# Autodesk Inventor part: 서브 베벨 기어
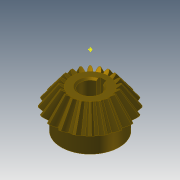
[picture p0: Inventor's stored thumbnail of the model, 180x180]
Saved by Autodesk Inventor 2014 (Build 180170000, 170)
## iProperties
Created: 2014-10
Part Number: 서브 베벨 기어
Material: Steel, Mild
Document SubType Name: Modeling
Designer: KYOUNG IL JANG
Categories: <?xml version="1.0" encoding="UTF-16"?> <MemberInstance><Categories><FamilyTemplate><FamilyTemplateParameter ValueType="xs:double" Id="1" ObjectReferenceKey="da
Mass: 134.866 g
Surface Area: 63.6518 cm^2
Volume: 17.1585 cm^3
Density: 7.86 g/cm^3
Appearance: Brindle
CustomPartVersion: 1
Company: 한국ATC센터
Author: KYOUNG IL JANG
Revision Number: 1
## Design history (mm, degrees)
node "맨 위 점"
node "메쉬 평면2"
sketch "톱니 본체 스케치"
  geometry: L1 (0, 0)-(18.003, -31.331); L2 (18.003, -31.331)-(21.664, -28.891); L3 (21.664, -28.891)-(0, 0); L4 (20, -30)-(0, 0); L5 (10.813, -18.818)-(13.012, -17.352); L6 (18.003, -31.331)-(10.813, -18.818); L7 (21.664, -28.891)-(13.012, -17.352); L8 (0, -39.387)-(0, 6.564) reference; L9 (0, -30)-(21.664, -30)
  constraints: 16 end point, 4 point on line, 3 perpendicular, 2 collinear, 1 horizontal alignment, 1 vertical alignment
  dimensions: "d0" = 40 diameter of L4.start L8 (= da_de); "d1" = 36.00616 diameter of L1.end L8 (= da_dfe); "d2" = 43.3282 diameter of L2.end L8 (= da_dae); "d3" = 14.4 distance between parallel lines of L2 L5 (= da_b); "d4" = 28.8906 vertical distance of L2.end L1.start (= da_ve)
revolve "톱니 본체" sketch "톱니 본체 스케치" stored, may be unused: angle "d5" = 90 deg
node "시작점"
node "톱니 평면"
sketch "시작 스케치"
  geometry: L1 (0, -23.505)-(0, 10.645) reference; L2 (-0.834, -2.928)-(0.834, -2.928); A1 r 8.898 centre (-9.698, -3.713) between (-0.834, -2.928) and (-3.903, 3.04); A2 r 8.898 centre (9.698, -3.713) between (3.903, 3.04) and (0.834, -2.928); A3 r 27.357 centre (0, -24.037) between (3.903, 3.04) and (-3.903, 3.04); 1 further point
  constraints: 6 point on circle, 3 centre point, 3 symmetric about line, 2 end point, 1 coincident, 1 perpendicular, 1 other
  dimensions: "d7" = 8.89846 radius of A1 (= fd_rr); "d8" = 9.69794 horizontal distance of point (0, -24.037) A1.centre (= fd_x); "d9" = 20.32439 vertical distance of point (0, -24.037) A1.centre (= fd_y); "d57" = 27.35701 radius of A3 (= 0.5 x fd_dva + 0.3 x da_he); "d58" = 21.10901 distance from line of A3.centre L2 (= 0.5 x fd_dva - 1.12 x da_he)
node "끝점"
  node "끝 평면"
sketch "3D 스케치 오른쪽"
  node "Helical Curve Right" dims "d65" = 229.90621 (computed from da_dm, da_delta, da_beta), "d66" = 31.5, "d67" = 40 (= da_de), "d68" = -5.88003 (= -da_delta), "d69" = 12.16458 (computed from fd_loft, da_delta)
node "끝 평면 오른쪽"
sketch "끝 스케치 오른쪽"
  geometry: L1 (0, -22.649)-(0, 12.15) reference; L2 (-0.497, -1.72)-(0.497, -1.72); A1 r 5.299 centre (-5.775, -2.187) between (-0.497, -1.72) and (-2.324, 1.834); A2 r 5.299 centre (5.775, -2.187) between (2.324, 1.834) and (0.497, -1.72); A3 r 16.291 centre (0, -14.29) between (2.324, 1.834) and (-2.324, 1.834); 1 further point
  constraints: 6 point on circle, 3 centre point, 3 symmetric about line, 2 end point, 1 coincident, 1 perpendicular, 1 other
  dimensions: "d70" = 5.77526 horizontal distance of A3.centre A1.centre (computed from fd_x, fd_ratio); "d71" = 12.10346 vertical distance of point (0, -14.29) A1.centre (computed from fd_y, fd_ratio); "d72" = 5.29916 radius of A1 (computed from fd_rr, fd_ratio); "d73" = 12.57071 distance from line of point (0, -14.29) L2 (computed from d58, fd_ratio); "d74" = 16.29149 radius of A3 (computed from d57, fd_ratio)
feature "로프트 오른쪽" sketch "끝 스케치 오른쪽" dims "d75" = 0, "d77" = 0, "d79" = 0, "d80" = 90 deg, "d85" = 20, "d92" = 90 deg, "d93" = 90 deg, "da_teethtype" = 0 [user parameter]
sketch "3D 스케치 왼쪽"
  node "Helical Curve Left" dims "d26" = 229.90621 (computed from da_dm, da_delta, da_beta), "d27" = 12.16458 (computed from fd_loft, da_delta), "d28" = 40 (= da_de), "d29" = -5.88003 (= -da_delta)
node "끝 평면 왼쪽"
sketch "끝 스케치 왼쪽" dims "d56" = 10.82768 (derived)
  geometry: L1 (0, -35.087)-(0, 18.089) reference; L2 (-0.497, -1.716)-(0.497, -1.716); A1 r 5.299 centre (-5.775, -2.183) between (-0.497, -1.716) and (-2.324, 1.838); A2 r 5.299 centre (5.775, -2.183) between (2.324, 1.838) and (0.497, -1.716); A3 r 16.291 centre (0, -14.287) between (2.324, 1.838) and (-2.324, 1.838); 2 further points; 1 other entity
  constraints: 6 point on circle, 3 centre point, 3 symmetric about line, 2 end point, 1 coincident, 2 other
  dimensions: "d30" = 5.29916 radius of A1 (computed from fd_rr, fd_ratio); "d31" = 5.77526 horizontal distance of point (0, -14.287) A1.centre (computed from fd_x, fd_ratio); "d32" = 12.10346 vertical distance of A1.centre point (0, -14.287) (computed from fd_y, fd_ratio); "d61" = 16.29149 radius of A3 (computed from d57, fd_ratio); "d62" = 12.57071 distance from line of point (0, -14.287) L2 (computed from d58, fd_ratio)
feature "로프트 왼쪽" sketch "끝 스케치 왼쪽" dims "d35" = 0, "d37" = 0, "d39" = 0, "d40" = 90 deg, "d84" = 10, "d90" = 90 deg, "d91" = 90 deg, "da_teethtype" = 0 [user parameter]
sketch "본체 스케치"
  geometry: L1 (0, -35.038)-(0, -19.531) reference; L2 (18.003, -31.331)-(10.813, -18.818) reference; L3 (10.813, -18.818)-(0, -18.818); L4 (18.003, -31.331)-(0, -31.331)
  constraints: 4 end point, 2 perpendicular, 2 point on line
revolve "본체 고정" sketch "본체 스케치" stored, may be unused: angle "d46" = 90 deg
sketch "Sketch6"
  geometry: L1 (20, -30)-(0, 0) reference; L2 (0, -37.8)-(0, 6.3) reference
feature "피치 지름" sketch "Sketch6" dims angle "d47" = 90 deg
sketch "스케치8"
  geometry: C1 r 17 at (0, 0); 1 further point
  constraints: 1 centre point, 1 coincident
  dimensions: "d94" = 34 diameter of C1
extrude "돌출1" join sketch "스케치8" distance "d95" = 10; taper "d96" = 0 deg
sketch "스케치9"
  geometry: 1 further point
hole "구멍1" sketch "스케치9" diameter "d97" = 12; stored, may be unused: countersink angle "d101" = 90 deg, drill point angle "d103" = 118 deg; dims "d98" = 6, "d99" = 4, "d100" = 2, "d102" = 8
sketch "스케치12"
  geometry: L1 (-2, 5.657)-(-2, 7.8); L2 (-2, 7.8)-(2, 7.8); L3 (2, 7.8)-(2, 5.657); A1 r 6 centre (0, 0) between (-2, 5.657) and (2, 5.657) reference; 1 further point
  constraints: 6 end point, 2 parallel, 2 point on circle, 1 perpendicular, 1 vertical
  dimensions: "d104" = 4 distance of L1.end L2.end; "d105" = 13.8 dimension on A1 L2
extrude "돌출2" cut sketch "스케치12" stored distance "d106" = 7; taper "d107" = 0 deg
chamfer "모따기1" distance "d108" = 1; stored, may be unused: second distance "d109" = 2, angle "d110" = 45 deg
body "Solid1"
feature "로프트" dims "d17" = 0, "d18" = 90 deg, "d19" = 0, "d20" = 90 deg, "d89" = 0, "da_teethtype" = 0 [user parameter]
pattern_circular "원형 패턴" dims angle "d22" = 360 deg, "d88" = 0, "da_teethtype" = 0 [user parameter]
pattern_circular "원형 패턴 오른쪽" dims angle "d82" = 360 deg, "da_teethtype" = 0 [user parameter]
pattern_circular "원형 패턴 왼쪽" dims angle "d42" = 360 deg, "da_teethtype" = 0 [user parameter]
sketch "스케치10"
  geometry: 1 further point
sketch "스케치11"
  geometry: 1 further point
sketch "끝 스케치"
  geometry: L1 (0, -15.359)-(0, 6.983) reference; L2 (-0.497, -1.72)-(0.497, -1.72); A1 r 5.299 centre (-5.775, -2.187) between (-0.497, -1.72) and (-2.324, 1.834); A2 r 5.299 centre (5.775, -2.187) between (2.324, 1.834) and (0.497, -1.72); A3 r 16.291 centre (0, -14.29) between (2.324, 1.834) and (-2.324, 1.834); 1 further point
  constraints: 6 point on circle, 3 centre point, 3 symmetric about line, 2 end point, 1 coincident, 1 other
  dimensions: "d12" = 5.29916 radius of A1 (computed from fd_rr, fd_ratio); "d15" = 5.77526 horizontal distance of A1.centre point (0, -14.29) (computed from fd_x, fd_ratio); "d16" = 12.10346 vertical distance of A1.centre point (0, -14.29) (computed from fd_y, fd_ratio); "d59" = 16.29149 radius of A3 (computed from d57, fd_ratio); "d60" = 12.57071 distance from line of A3.centre L2 (computed from d58, fd_ratio)
body "Srf1"
other parameters: "da_b" = 14.4 [user parameter; used in 2 equation terms], "da_de" = 40 [user parameter; used in 4 equation terms], "da_dae" = 43.3282 [user parameter; used in 2 equation terms], "da_dfe" = 36.00616 [user parameter; used in 1 equation term], "da_le" = 36.05551 [user parameter; used in 1 equation term], "da_omega" = 90 deg [user parameter; used in 1 equation term], "da_beta" = 0 [user parameter; used in 2 equation terms], "da_delta" = 5.88003 [user parameter; used in 8 equation terms], "da_alpha" = 20 deg [user parameter; used in 2 equation terms], "da_he" = 4.4 [user parameter; used in 4 equation terms], "da_ve" = 28.8906 [user parameter; used in 1 equation term], "fd_dv" = 48.07402 (computed from da_de, da_delta) [user parameter; used in 1 equation term], "fd_dva" = 52.07402 (computed from da_dae, da_delta) [user parameter; used in 3 equation terms], "fd_dvb" = 45.1748 (computed from fd_dv, da_alpha) [user parameter; used in 2 equation terms], "da_zv" = 240.37008 [user parameter; used in 1 equation term], "fd_loft" = 14.62 (= da_b + 0.05 x da_he) [user parameter; used in 4 equation terms], "fd_ratio" = 5.95514 (computed from da_le, fd_loft) [user parameter; used in 15 equation terms], "fd_rr" = 8.89846 (computed from fd_dd, fd_dvb) [user parameter; used in 6 equation terms], "fd_angle" = 0.66075 (computed from da_zv) [user parameter; used in 4 equation terms], "fd_x1" = 1.58709 (computed from da_dvw, fd_angle) [user parameter; used in 1 equation term], "fd_y1" = 23.98456 (computed from da_dvw, fd_angle) [user parameter; used in 1 equation term], "fd_x2" = 8.11084 (computed from fd_rr, fd_angle2, fd_angle) [user parameter; used in 1 equation term], "fd_y2" = 3.66016 (computed from fd_rr, fd_angle2, fd_angle) [user parameter; used in 1 equation term], "fd_x" = 9.69794 (= fd_x1 + fd_x2) [user parameter; used in 4 equation terms], "fd_y" = 20.32439 (= fd_y1 - fd_y2) [user parameter; used in 4 equation terms], "fd_angle2" = 3.57832 (computed from fd_dvb, fd_dd, da_alpha) [user parameter; used in 2 equation terms], "fd_dd" = 48.55402 (= fd_dva - 0.8 x da_he) [user parameter; used in 2 equation terms], "da_dvw" = 48.07402 [user parameter; used in 2 equation terms], "d11" = 14.62 (= fd_loft), "da_dm" = 32.01232 [user parameter; used in 2 equation terms], "da_x" = 0 [user parameter], "da_m" = 2 [user parameter], "d48" = 0, "d49" = 0, "d50" = 90 deg (= da_omega), "d51" = 9 deg (computed from da_z), "d52" = 0, "d53" = 0, "d54" = 0
